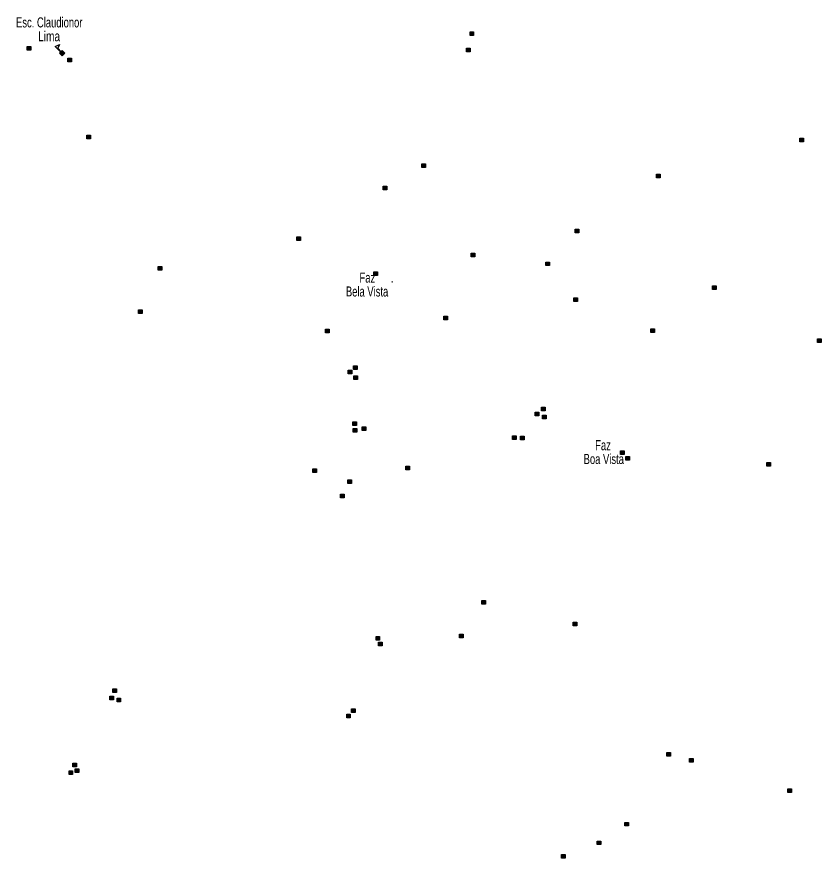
# Model space of a CAD drawing. Extents: x 447.8 to 473.9, y 7733.1 to 7760.8.
# Drawn here: x 460.98 to 467.39, y 7740.23 to 7746.93 of the extents above; entities that cross this region are included whole.
import ezdxf
from ezdxf.enums import TextEntityAlignment as Align

# ---------------------------------------------------------------- set-up
doc = ezdxf.new("R2010")
doc.units = 0
doc.header["$LTSCALE"] = 0.032
doc.layers.add('2', color=7, linetype='Continuous', lineweight=25)
doc.layers.add('4', color=7, linetype='Continuous', lineweight=25)
doc.layers.add('61', color=7, linetype='Continuous')

msp = doc.modelspace()

# ---------------------------------------------------------------- hatches: boundary and pattern name
at = {"layer": '2'}
for points in [[(464.5917, 7746.8093), (464.6207, 7746.8093), (464.6207, 7746.7803), (464.5917, 7746.7803)], [(461.0646, 7746.6926), (461.0936, 7746.6926), (461.0936, 7746.6636), (461.0646, 7746.6636)], [(464.5642, 7746.6788), (464.5932, 7746.6788), (464.5932, 7746.6498), (464.5642, 7746.6498)], [(461.3896, 7746.5987), (461.4186, 7746.5987), (461.4186, 7746.5697), (461.3896, 7746.5697)], [(461.5406, 7745.9853), (461.5696, 7745.9853), (461.5696, 7745.9563), (461.5406, 7745.9563)], [(467.217, 7745.9624), (467.246, 7745.9624), (467.246, 7745.9334), (467.217, 7745.9334)], [(464.2094, 7745.7564), (464.2384, 7745.7564), (464.2384, 7745.7274), (464.2094, 7745.7274)], [(466.0772, 7745.6763), (466.1062, 7745.6763), (466.1062, 7745.6473), (466.0772, 7745.6473)], [(463.9004, 7745.5802), (463.9294, 7745.5802), (463.9294, 7745.5512), (463.9004, 7745.5512)], [(465.4294, 7745.2369), (465.4584, 7745.2369), (465.4584, 7745.2079), (465.4294, 7745.2079)], [(463.2138, 7745.1751), (463.2428, 7745.1751), (463.2428, 7745.1461), (463.2138, 7745.1461)], [(464.6008, 7745.0469), (464.6298, 7745.0469), (464.6298, 7745.0179), (464.6008, 7745.0179)], [(462.1083, 7744.9393), (462.1373, 7744.9393), (462.1373, 7744.9103), (462.1083, 7744.9103)], [(465.1959, 7744.9759), (465.2249, 7744.9759), (465.2249, 7744.9469), (465.1959, 7744.9469)], [(463.8272, 7744.8981), (463.8562, 7744.8981), (463.8562, 7744.8691), (463.8272, 7744.8691)], [(466.5235, 7744.7859), (466.5525, 7744.7859), (466.5525, 7744.7569), (466.5235, 7744.7569)], [(465.418, 7744.6898), (465.447, 7744.6898), (465.447, 7744.6608), (465.418, 7744.6608)], [(461.9526, 7744.596), (461.9816, 7744.596), (461.9816, 7744.567), (461.9526, 7744.567)], [(464.3834, 7744.5456), (464.4124, 7744.5456), (464.4124, 7744.5166), (464.3834, 7744.5166)], [(463.4404, 7744.4403), (463.4694, 7744.4403), (463.4694, 7744.4113), (463.4404, 7744.4113)], [(466.0314, 7744.4426), (466.0604, 7744.4426), (466.0604, 7744.4136), (466.0314, 7744.4136)], [(467.3589, 7744.3648), (467.3879, 7744.3648), (467.3879, 7744.3358), (467.3589, 7744.3358)], [(463.6647, 7744.1496), (463.6937, 7744.1496), (463.6937, 7744.1206), (463.6647, 7744.1206)], [(463.6212, 7744.1153), (463.6502, 7744.1153), (463.6502, 7744.0863), (463.6212, 7744.0863)], [(463.667, 7744.0695), (463.696, 7744.0695), (463.696, 7744.0405), (463.667, 7744.0405)], [(465.1616, 7743.82), (465.1906, 7743.82), (465.1906, 7743.791), (465.1616, 7743.791)], [(465.1113, 7743.7811), (465.1403, 7743.7811), (465.1403, 7743.7521), (465.1113, 7743.7521)], [(465.1685, 7743.756), (465.1975, 7743.756), (465.1975, 7743.727), (465.1685, 7743.727)], [(463.6578, 7743.7033), (463.6868, 7743.7033), (463.6868, 7743.6743), (463.6578, 7743.6743)], [(463.7334, 7743.6644), (463.7624, 7743.6644), (463.7624, 7743.6354), (463.7334, 7743.6354)], [(463.6624, 7743.6507), (463.6914, 7743.6507), (463.6914, 7743.6217), (463.6624, 7743.6217)], [(464.9304, 7743.5912), (464.9594, 7743.5912), (464.9594, 7743.5622), (464.9304, 7743.5622)], [(464.9945, 7743.5889), (465.0235, 7743.5889), (465.0235, 7743.5599), (464.9945, 7743.5599)], [(465.791, 7743.4721), (465.82, 7743.4721), (465.82, 7743.4431), (465.791, 7743.4431)], [(465.8322, 7743.4264), (465.8612, 7743.4264), (465.8612, 7743.3974), (465.8322, 7743.3974)], [(463.3397, 7743.3302), (463.3687, 7743.3302), (463.3687, 7743.3012), (463.3397, 7743.3012)], [(464.0813, 7743.3508), (464.1103, 7743.3508), (464.1103, 7743.3218), (464.0813, 7743.3218)], [(466.9561, 7743.3806), (466.9851, 7743.3806), (466.9851, 7743.3516), (466.9561, 7743.3516)], [(463.6189, 7743.241), (463.6479, 7743.241), (463.6479, 7743.212), (463.6189, 7743.212)], [(463.5594, 7743.1265), (463.5884, 7743.1265), (463.5884, 7743.0975), (463.5594, 7743.0975)], [(464.6855, 7742.2819), (464.7145, 7742.2819), (464.7145, 7742.2529), (464.6855, 7742.2529)], [(465.4134, 7742.108), (465.4424, 7742.108), (465.4424, 7742.079), (465.4134, 7742.079)], [(463.8432, 7741.9935), (463.8722, 7741.9935), (463.8722, 7741.9645), (463.8432, 7741.9645)], [(464.507, 7742.0141), (464.536, 7742.0141), (464.536, 7741.9851), (464.507, 7741.9851)], [(463.8638, 7741.9501), (463.8928, 7741.9501), (463.8928, 7741.9211), (463.8638, 7741.9211)], [(461.7237, 7741.5198), (461.7527, 7741.5198), (461.7527, 7741.4908), (461.7237, 7741.4908)], [(461.7466, 7741.577), (461.7756, 7741.577), (461.7756, 7741.548), (461.7466, 7741.548)], [(461.781, 7741.5037), (461.81, 7741.5037), (461.81, 7741.4747), (461.781, 7741.4747)], [(463.6487, 7741.419), (463.6777, 7741.419), (463.6777, 7741.39), (463.6487, 7741.39)], [(463.6098, 7741.3756), (463.6388, 7741.3756), (463.6388, 7741.3466), (463.6098, 7741.3466)], [(466.1595, 7741.0711), (466.1885, 7741.0711), (466.1885, 7741.0421), (466.1595, 7741.0421)], [(461.4285, 7740.9864), (461.4575, 7740.9864), (461.4575, 7740.9574), (461.4285, 7740.9574)], [(466.3404, 7741.0231), (466.3694, 7741.0231), (466.3694, 7740.9941), (466.3404, 7740.9941)], [(461.3987, 7740.9246), (461.4277, 7740.9246), (461.4277, 7740.8956), (461.3987, 7740.8956)], [(461.4491, 7740.9407), (461.4781, 7740.9407), (461.4781, 7740.9117), (461.4491, 7740.9117)], [(467.1232, 7740.7827), (467.1522, 7740.7827), (467.1522, 7740.7537), (467.1232, 7740.7537)], [(465.8254, 7740.5149), (465.8544, 7740.5149), (465.8544, 7740.4859), (465.8254, 7740.4859)], [(465.6034, 7740.3662), (465.6324, 7740.3662), (465.6324, 7740.3372), (465.6034, 7740.3372)], [(465.3195, 7740.2586), (465.3485, 7740.2586), (465.3485, 7740.2296), (465.3195, 7740.2296)]]:
    msp.add_hatch(color=256, dxfattribs=at).paths.add_polyline_path(points)
at = {"layer": '4'}
msp.add_hatch(color=256, dxfattribs=at).paths.add_polyline_path([(461.3452, 7746.6167), (461.3241, 7746.638), (461.3454, 7746.6592), (461.3665, 7746.6379)])

# ---------------------------------------------------------------- linework, layer by layer
at = {"layer": '2'}
for points in [[(464.5917, 7746.8093), (464.6207, 7746.8093), (464.6207, 7746.7803), (464.5917, 7746.7803)], [(461.0646, 7746.6926), (461.0936, 7746.6926), (461.0936, 7746.6636), (461.0646, 7746.6636)], [(464.5642, 7746.6788), (464.5932, 7746.6788), (464.5932, 7746.6498), (464.5642, 7746.6498)], [(461.3896, 7746.5987), (461.4186, 7746.5987), (461.4186, 7746.5697), (461.3896, 7746.5697)], [(461.5406, 7745.9853), (461.5696, 7745.9853), (461.5696, 7745.9563), (461.5406, 7745.9563)], [(467.217, 7745.9624), (467.246, 7745.9624), (467.246, 7745.9334), (467.217, 7745.9334)], [(464.2094, 7745.7564), (464.2384, 7745.7564), (464.2384, 7745.7274), (464.2094, 7745.7274)], [(466.0772, 7745.6763), (466.1062, 7745.6763), (466.1062, 7745.6473), (466.0772, 7745.6473)], [(463.9004, 7745.5802), (463.9294, 7745.5802), (463.9294, 7745.5512), (463.9004, 7745.5512)], [(465.4294, 7745.2369), (465.4584, 7745.2369), (465.4584, 7745.2079), (465.4294, 7745.2079)], [(463.2138, 7745.1751), (463.2428, 7745.1751), (463.2428, 7745.1461), (463.2138, 7745.1461)], [(464.6008, 7745.0469), (464.6298, 7745.0469), (464.6298, 7745.0179), (464.6008, 7745.0179)], [(462.1083, 7744.9393), (462.1373, 7744.9393), (462.1373, 7744.9103), (462.1083, 7744.9103)], [(465.1959, 7744.9759), (465.2249, 7744.9759), (465.2249, 7744.9469), (465.1959, 7744.9469)], [(463.8272, 7744.8981), (463.8562, 7744.8981), (463.8562, 7744.8691), (463.8272, 7744.8691)], [(466.5235, 7744.7859), (466.5525, 7744.7859), (466.5525, 7744.7569), (466.5235, 7744.7569)], [(465.418, 7744.6898), (465.447, 7744.6898), (465.447, 7744.6608), (465.418, 7744.6608)], [(461.9526, 7744.596), (461.9816, 7744.596), (461.9816, 7744.567), (461.9526, 7744.567)], [(464.3834, 7744.5456), (464.4124, 7744.5456), (464.4124, 7744.5166), (464.3834, 7744.5166)], [(463.4404, 7744.4403), (463.4694, 7744.4403), (463.4694, 7744.4113), (463.4404, 7744.4113)], [(466.0314, 7744.4426), (466.0604, 7744.4426), (466.0604, 7744.4136), (466.0314, 7744.4136)], [(467.3589, 7744.3648), (467.3879, 7744.3648), (467.3879, 7744.3358), (467.3589, 7744.3358)], [(463.6647, 7744.1496), (463.6937, 7744.1496), (463.6937, 7744.1206), (463.6647, 7744.1206)], [(463.6212, 7744.1153), (463.6502, 7744.1153), (463.6502, 7744.0863), (463.6212, 7744.0863)], [(463.667, 7744.0695), (463.696, 7744.0695), (463.696, 7744.0405), (463.667, 7744.0405)], [(465.1616, 7743.82), (465.1906, 7743.82), (465.1906, 7743.791), (465.1616, 7743.791)], [(465.1113, 7743.7811), (465.1403, 7743.7811), (465.1403, 7743.7521), (465.1113, 7743.7521)], [(465.1685, 7743.756), (465.1975, 7743.756), (465.1975, 7743.727), (465.1685, 7743.727)], [(463.6578, 7743.7033), (463.6868, 7743.7033), (463.6868, 7743.6743), (463.6578, 7743.6743)], [(463.7334, 7743.6644), (463.7624, 7743.6644), (463.7624, 7743.6354), (463.7334, 7743.6354)], [(463.6624, 7743.6507), (463.6914, 7743.6507), (463.6914, 7743.6217), (463.6624, 7743.6217)], [(464.9304, 7743.5912), (464.9594, 7743.5912), (464.9594, 7743.5622), (464.9304, 7743.5622)], [(464.9945, 7743.5889), (465.0235, 7743.5889), (465.0235, 7743.5599), (464.9945, 7743.5599)], [(465.791, 7743.4721), (465.82, 7743.4721), (465.82, 7743.4431), (465.791, 7743.4431)], [(465.8322, 7743.4264), (465.8612, 7743.4264), (465.8612, 7743.3974), (465.8322, 7743.3974)], [(463.3397, 7743.3302), (463.3687, 7743.3302), (463.3687, 7743.3012), (463.3397, 7743.3012)], [(464.0813, 7743.3508), (464.1103, 7743.3508), (464.1103, 7743.3218), (464.0813, 7743.3218)], [(466.9561, 7743.3806), (466.9851, 7743.3806), (466.9851, 7743.3516), (466.9561, 7743.3516)], [(463.6189, 7743.241), (463.6479, 7743.241), (463.6479, 7743.212), (463.6189, 7743.212)], [(463.5594, 7743.1265), (463.5884, 7743.1265), (463.5884, 7743.0975), (463.5594, 7743.0975)], [(464.6855, 7742.2819), (464.7145, 7742.2819), (464.7145, 7742.2529), (464.6855, 7742.2529)], [(465.4134, 7742.108), (465.4424, 7742.108), (465.4424, 7742.079), (465.4134, 7742.079)], [(463.8432, 7741.9935), (463.8722, 7741.9935), (463.8722, 7741.9645), (463.8432, 7741.9645)], [(464.507, 7742.0141), (464.536, 7742.0141), (464.536, 7741.9851), (464.507, 7741.9851)], [(463.8638, 7741.9501), (463.8928, 7741.9501), (463.8928, 7741.9211), (463.8638, 7741.9211)], [(461.7237, 7741.5198), (461.7527, 7741.5198), (461.7527, 7741.4908), (461.7237, 7741.4908)], [(461.7466, 7741.577), (461.7756, 7741.577), (461.7756, 7741.548), (461.7466, 7741.548)], [(461.781, 7741.5037), (461.81, 7741.5037), (461.81, 7741.4747), (461.781, 7741.4747)], [(463.6487, 7741.419), (463.6777, 7741.419), (463.6777, 7741.39), (463.6487, 7741.39)], [(463.6098, 7741.3756), (463.6388, 7741.3756), (463.6388, 7741.3466), (463.6098, 7741.3466)], [(466.1595, 7741.0711), (466.1885, 7741.0711), (466.1885, 7741.0421), (466.1595, 7741.0421)], [(461.4285, 7740.9864), (461.4575, 7740.9864), (461.4575, 7740.9574), (461.4285, 7740.9574)], [(466.3404, 7741.0231), (466.3694, 7741.0231), (466.3694, 7740.9941), (466.3404, 7740.9941)], [(461.3987, 7740.9246), (461.4277, 7740.9246), (461.4277, 7740.8956), (461.3987, 7740.8956)], [(461.4491, 7740.9407), (461.4781, 7740.9407), (461.4781, 7740.9117), (461.4491, 7740.9117)], [(467.1232, 7740.7827), (467.1522, 7740.7827), (467.1522, 7740.7537), (467.1232, 7740.7537)], [(465.8254, 7740.5149), (465.8544, 7740.5149), (465.8544, 7740.4859), (465.8254, 7740.4859)], [(465.6034, 7740.3662), (465.6324, 7740.3662), (465.6324, 7740.3372), (465.6034, 7740.3372)], [(465.3195, 7740.2586), (465.3485, 7740.2586), (465.3485, 7740.2296), (465.3195, 7740.2296)]]:
    msp.add_lwpolyline(points, close=True, dxfattribs=at)
at = {"layer": '4'}
msp.add_line((461.3329, 7746.6468), (461.3365, 7746.6504), dxfattribs=at)
for points in [[(461.3329, 7746.6468), (461.2889, 7746.6912), (461.3225, 7746.707), (461.3086, 7746.6784), (461.3365, 7746.6504)], [(461.3452, 7746.6167), (461.3241, 7746.638), (461.3454, 7746.6592), (461.3665, 7746.6379)]]:
    msp.add_lwpolyline(points, close=True, dxfattribs=at)

# ---------------------------------------------------------------- texts
at = {"layer": '61'}
for s, width, p in [('Esc. Claudionor', 0.7, (461.5057, 7746.8436)), ('       Lima        ', 0.75, (461.5057, 7746.7336)), ('Faz      .', 0.7, (463.9823, 7744.8113)), ('Bela Vista  ', 0.7, (463.9823, 7744.7013)), ('  Faz     ', 0.7, (465.8172, 7743.4776)), ('Boa Vista', 0.7, (465.8172, 7743.3676))]:
    msp.add_text(s, height=0.08, dxfattribs=dict(at, width=width)).set_placement(p, align=Align.RIGHT)

doc.saveas('drawing.dxf')
